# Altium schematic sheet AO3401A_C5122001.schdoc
size 127 x 101 mm
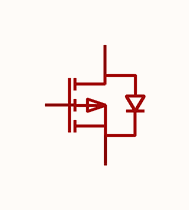
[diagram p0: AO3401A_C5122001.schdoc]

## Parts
Q?  ao3401a  [SOT-23-3_L2.9-W1.3-P1.90-LS2.4-BR]  (value not drawn)

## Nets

Not connected (* = marked no-connect by the designer): Q? 1(G) 2(S) 3(D)

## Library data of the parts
Q? = ao3401a: 漏源电压(Vdss):30V;连续漏极电流(Id):4.2A;导通电阻(RDS(on)):55mΩ@10V,4.2A;耗散功率(Pd):1.2W;阈值电压(Vgs(th)):-;; Manufacturer: TECH PUBLIC(台舟); Symbol: AO3401A_C5122001; AddInBom: yes; ModelId: c62791f0466c4ae2a892c056b845b0ca; ModelName: SOT-23-3P_L2.9-W1.3-H1.0-LS2.4-P0.95; ModelTransform: 98.425,114.173,0,180,0,0,0.0005,-0.0005,0; Drain to Source Voltage: 30V; Pd - Power Dissipation: 1.2W; Gate Charge(Qg): 8.5nC; Input Capacitance(Ciss): 880pF@15V; Reverse Transfer Capacitance (Crss@Vds): 65pF@15V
